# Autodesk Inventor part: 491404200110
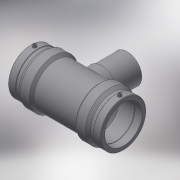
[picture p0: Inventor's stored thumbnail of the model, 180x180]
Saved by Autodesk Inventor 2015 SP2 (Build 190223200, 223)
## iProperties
Created: 2017-06
Part Number: 491404200110
Material: Generic
Description: PLASSON REDUCING TEE 200x110x200
Document SubType Name: Modeling
Designer: KIM
Mass: 8228.37 g
Surface Area: 7217.69 cm^2
Volume: 8228.37 cm^3
Density: 1 g/cm^3
Appearance: Default
Author: KIM
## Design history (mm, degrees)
derived "491404.ipt"
feature "Solid1::491404.ipt"
tag "TaggingFeature1"
body "Solid1"
other parameters: "d0" = 451, "d2" = 261, "d3" = 114, "d4" = 90.2, "d5" = 234.9, "d8" = 168 deg, "d10" = 45.6, "d11" = 15.2, "d13" = 451, "d14" = 17.6296, "d19" = 3.52592, "d20" = 168 deg, "d22" = 242.73, "d23" = 261, "d25" = 135 deg, "d26" = 315.7, "d29" = 125, "d30" = 15, "d31" = 180.4, "d34" = 5 deg, "d35" = 15, "d39" = 5 deg, "d41" = 4, "d42" = 14, "d43" = 0, "d45" = 4, "d46" = 6, "d47" = 0, "d51" = 0, "d52" = 88, "d54" = 0, "d55" = 234.9, "d56" = 261, "d57" = 157.85, "d58" = 135 deg, "d59" = 114, "d60" = 114, "d61" = 135 deg, "d72" = 205.205, "d73" = 102.6025, "d75" = 115.5, "d77" = 0, "d78" = 88, "d80" = 0, "d82" = 79.5, "d83" = 0, "d84" = 3, "d85" = 0, "d86" = 38, "d87" = 237.8754, "d88" = 15.2, "d89" = 3, "d90" = 0, "L_" = 451, "L_1" = 114, "D_" = 261, "A_" = 125, "d_2" = 12
